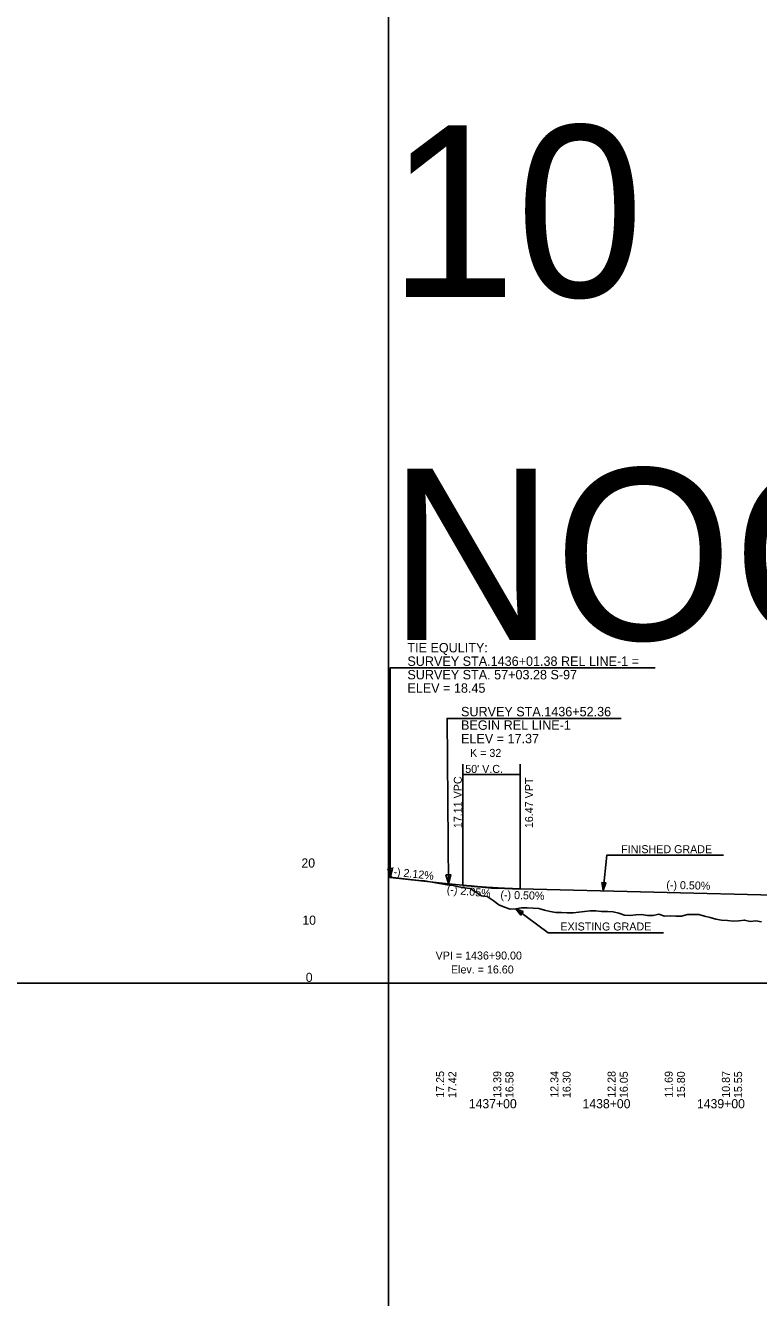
# Model space of a CAD drawing. Extents: x 2360994 to 2383826, y 330623 to 403123.
# Drawn here: x 2368508 to 2369149, y 376598 to 377710 of the extents above; entities that cross this region are included whole.
import ezdxf

# ---------------------------------------------------------------- set-up
doc = ezdxf.new("R2010")
doc.units = 0
for name, color, linetype in [('RD_DDB_ElevTX', 7, 'Continuous'), ('RD_DDB_GradeTX', 7, 'Continuous'), ('RD_DDB_Profile_EX', 7, 'Continuous'), ('RD_DDB_Profile_Lbl', 7, 'Continuous'), ('RD_DDB_Profile_PR', 7, 'Continuous'), ('RD_DDB_StaTX', 7, 'Continuous'), ('RD_DDB_StripGrade', 7, 'Continuous'), ('RD_DDB_VCLbl', 7, 'Continuous'), ('RD_GPK_Profile_Cell', 7, 'Continuous'), ('RD_SHT_Misc1', 7, 'Continuous'), ('RD_TX_Profile', 7, 'Continuous')]:
    doc.layers.add(name, color=color, linetype=linetype)

msp = doc.modelspace()

# ---------------------------------------------------------------- linework, layer by layer
at = {"layer": 'RD_DDB_GradeTX'}
for p in [(2368890.6, 376958.4), (2368940.6, 376955.3)]:
    msp.add_line(p, (2368915.6, 376955.9), dxfattribs=at)
at = {"layer": 'RD_DDB_Profile_EX'}
msp.add_lwpolyline([(2368826.9, 376965.4), (2368831.9, 376964.9), (2368836.9, 376964.3), (2368841.9, 376963.8), (2368846.9, 376963.2), (2368851.9, 376962.7), (2368856.9, 376962.2), (2368861.9, 376961.5), (2368866.9, 376960.6), (2368871.9, 376959.8), (2368876.9, 376958.9), (2368881.9, 376958.1), (2368886.9, 376957.2), (2368891.9, 376956.2), (2368896.9, 376955.5), (2368901.9, 376952.5), (2368906.9, 376949.3), (2368911.9, 376948.6), (2368916.9, 376945), (2368921.9, 376941.4), (2368926.9, 376939.2), (2368931.9, 376937.5), (2368936.9, 376937.9), (2368941.9, 376938.6), (2368946.9, 376938.8), (2368951.9, 376938.5), (2368956.9, 376938.1), (2368961.9, 376936.6), (2368966.9, 376935.4), (2368971.9, 376934.7), (2368976.9, 376934.5), (2368981.9, 376934.4), (2368986.9, 376934.3), (2368991.9, 376934.9), (2368996.9, 376935.4), (2369001.9, 376936), (2369006.9, 376936.1), (2369011.9, 376935.4), (2369016.9, 376935.5), (2369021.9, 376935.2), (2369026.9, 376934), (2369031.9, 376932.4), (2369036.9, 376932.1), (2369041.9, 376932.5), (2369046.9, 376932.8), (2369051.9, 376932.1), (2369056.9, 376932), (2369061.9, 376933.1), (2369066.9, 376931.5), (2369071.9, 376931.6), (2369076.9, 376931.3), (2369081.9, 376931.3), (2369086.9, 376933), (2369091.9, 376932.9), (2369096.9, 376933), (2369101.9, 376931.3), (2369106.9, 376930.3), (2369111.9, 376928.9), (2369116.9, 376927.9), (2369121.9, 376927.5), (2369126.9, 376927.1), (2369131.9, 376927.4), (2369136.9, 376928), (2369141.9, 376926.8), (2369146.9, 376927.2), (2369151.9, 376926.5)], dxfattribs=at)
at = {"layer": 'RD_DDB_Profile_PR'}
for p, q in [((2368826.9, 376965.1), (2368877.9, 376959.7)), ((2368877.9, 376959.7), (2368890.6, 376958.4)), ((2368940.6, 376955.3), (2369750.6, 376935))]:
    msp.add_line(p, q, dxfattribs=at)
msp.add_spline([(2368890.6, 376958.4), (2368891.6, 376958.3), (2368892.6, 376958.2), (2368893.6, 376958.1), (2368894.6, 376958), (2368895.6, 376957.9), (2368896.6, 376957.8), (2368897.6, 376957.8), (2368898.6, 376957.7), (2368899.6, 376957.6), (2368900.6, 376957.5), (2368901.6, 376957.4), (2368902.6, 376957.3), (2368903.6, 376957.2), (2368904.6, 376957.2), (2368905.6, 376957.1), (2368906.6, 376957), (2368907.6, 376956.9), (2368908.6, 376956.8), (2368909.6, 376956.8), (2368910.6, 376956.7), (2368911.6, 376956.6), (2368912.6, 376956.6), (2368913.6, 376956.5), (2368914.6, 376956.4), (2368915.6, 376956.4), (2368916.6, 376956.3), (2368917.6, 376956.2), (2368918.6, 376956.2), (2368919.6, 376956.1), (2368920.6, 376956.1), (2368921.6, 376956), (2368922.6, 376956), (2368923.6, 376955.9), (2368924.6, 376955.8), (2368925.6, 376955.8), (2368926.6, 376955.8), (2368927.6, 376955.7), (2368928.6, 376955.7), (2368929.6, 376955.6), (2368930.6, 376955.6), (2368931.6, 376955.5), (2368932.6, 376955.5), (2368933.6, 376955.5), (2368934.6, 376955.4), (2368935.6, 376955.4), (2368936.6, 376955.4), (2368937.6, 376955.3), (2368938.6, 376955.3), (2368939.6, 376955.3), (2368940.6, 376955.3)], degree=3, dxfattribs=at)
at = {"layer": 'RD_DDB_VCLbl'}
for p, q in [((2368890.6, 377064.3), (2368890.6, 376958.4)), ((2368940.6, 377064.3), (2368940.6, 376955.3)), ((2368890.6, 377055.4), (2368940.6, 377055.4))]:
    msp.add_line(p, q, dxfattribs=at)
at = {"layer": 'RD_GPK_Profile_Cell'}
for q in [(2368825.6, 378122.9), (2370425.6, 376872.9), (2368825.6, 375622.9)]:
    msp.add_line((2368825.6, 376872.9), q, dxfattribs=at)
at = {"layer": 'RD_SHT_Misc1'}
msp.add_line((2368825.6, 376872.9), (2363729.6, 376872.9), dxfattribs=at)
at = {"layer": 'RD_TX_Profile'}
for p, q in [((2369058.8, 377148.5), (2368837, 377148.5)), ((2369029, 377104.4), (2368883.9, 377104.4)), ((2369118.6, 376984.8), (2369024, 376984.8)), ((2369065.9, 376916.9), (2368970.8, 376916.9))]:
    msp.add_line(p, q, dxfattribs=at)
for points in [[(2368837, 377148.5), (2368826.8, 377148.5), (2368826.9, 376965.1)], [(2368883.9, 377104.4), (2368876.7, 377104.4), (2368877.9, 376959.7)], [(2369024, 376984.8), (2369016.5, 376984.8), (2369013.2, 376954)], [(2368970.8, 376916.9), (2368965.2, 376916.9), (2368936.9, 376937.9)]]:
    msp.add_lwpolyline(points, dxfattribs=at)
for points in [[(2368824.8, 376973.1), (2368826.9, 376965.1), (2368829.1, 376973.1)], [(2368875.7, 376967.7), (2368877.9, 376959.7), (2368880, 376967.7)], [(2369012.1, 376960.9), (2369013.2, 376954), (2369015.7, 376960.5)], [(2368943.4, 376935.4), (2368936.9, 376937.9), (2368941.3, 376932.4)]]:
    msp.add_lwpolyline(points, close=True, dxfattribs=at)

# ---------------------------------------------------------------- texts
at = {"layer": 'RD_DDB_ElevTX'}
for s, p in [('20', (2368749.3, 376973.9)), ('10', (2368750.1, 376923.9)), ('0', (2368753.1, 376873.9))]:
    msp.add_text(s, height=8, dxfattribs=at).set_placement(p)
at = {"layer": 'RD_DDB_GradeTX'}
for s, rotation, p in [('(-) 2.12%', 353.9536, (2368826.4, 376967.2)), ('(-) 0.50%', 358.5679, (2369068.4, 376955.4)), ('(-) 2.05%', 354.1523, (2368876.2, 376951.6)), ('(-) 0.50%', 358.5679, (2368923.3, 376946.7))]:
    msp.add_text(s, height=7, rotation=rotation, dxfattribs=at).set_placement(p)
at = {"layer": 'RD_DDB_Profile_Lbl'}
for s, p in [('VPI = 1436+90.00', (2368866.7, 376893.5)), ('Elev. = 16.60', (2368880.1, 376881.3))]:
    msp.add_text(s, height=7, dxfattribs=at).set_placement(p)
at = {"layer": 'RD_DDB_StaTX'}
for s, p in [('1437+00', (2368895.7, 376763.4)), ('1438+00', (2368995.2, 376763.4)), ('1439+00', (2369095.3, 376763.4))]:
    msp.add_text(s, height=8, dxfattribs=at).set_placement(p)
at = {"layer": 'RD_DDB_StripGrade'}
for s, p in [('17.11 VPC', (2368889.6, 377008.4)), ('16.47 VPT', (2368951.9, 377008.4)), ('17.25', (2368874.1, 376772.6)), ('17.42', (2368884.8, 376772.3)), ('13.39', (2368924.1, 376772.6)), ('16.58', (2368934.8, 376772.3)), ('12.34', (2368974.1, 376772.6)), ('16.30', (2368984.8, 376772.3)), ('12.28', (2369024.1, 376772.6)), ('16.05', (2369034.8, 376772.3)), ('11.69', (2369074.1, 376772.6)), ('15.80', (2369084.8, 376772.3)), ('10.87', (2369124.1, 376772.6)), ('15.55', (2369134.8, 376772.3))]:
    msp.add_text(s, height=7, rotation=90, dxfattribs=at).set_placement(p)
at = {"layer": 'RD_DDB_VCLbl'}
for s, p in [('K = 32', (2368896.8, 377070.7)), ("50' V.C.", (2368892.6, 377056.7))]:
    msp.add_text(s, height=7, dxfattribs=at).set_placement(p)
at = {"layer": 'RD_GPK_Profile_Cell'}
for s, p in [('10', (2368825.6, 377472.9)), ('NOGAP', (2368825.6, 377172.9))]:
    msp.add_text(s, height=150, dxfattribs=at).set_placement(p)
at = {"layer": 'RD_TX_Profile'}
for s, height, p in [('TIE EQULITY:', 8.235, (2368842, 377162.1)), ('SURVEY STA.1436+01.38 REL LINE-1 =', 8.235, (2368842, 377150.3)), ('SURVEY STA. 57+03.28 S-97', 8.235, (2368842, 377138.5)), ('ELEV = 18.45', 8.235, (2368842, 377126.8)), ('SURVEY STA.1436+52.36', 8.235, (2368888.9, 377106.2)), ('BEGIN REL LINE-1', 8.235, (2368888.9, 377094.4)), ('ELEV = 17.37', 8.235, (2368888.9, 377082.6)), ('FINISHED GRADE', 7, (2369029, 376986.5)), ('EXISTING GRADE', 7, (2368975.8, 376918.9))]:
    msp.add_text(s, height=height, dxfattribs=at).set_placement(p)

doc.saveas('drawing.dxf')
